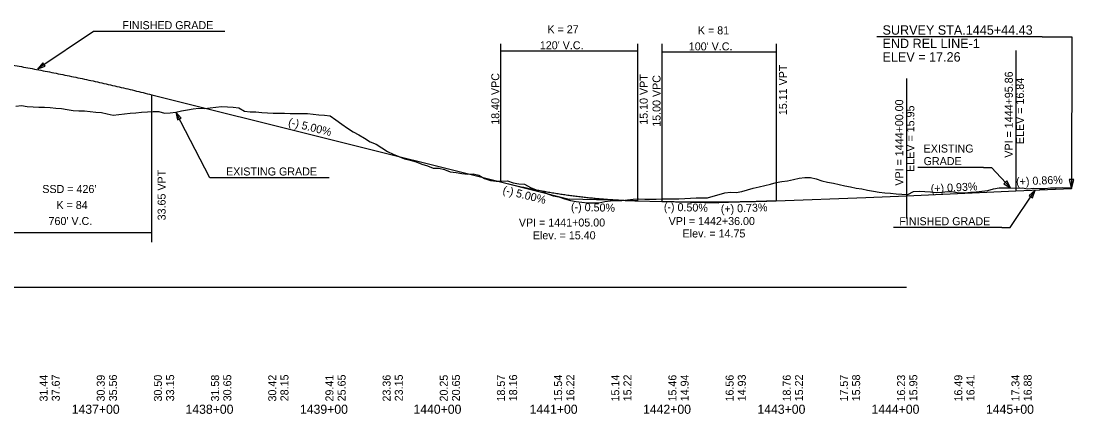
# Model space of a CAD drawing. Extents: x 2360994 to 2383826, y 330623 to 403123.
# Drawn here: x 2371951 to 2372872, y 366762 to 367106 of the extents above; entities that cross this region are included whole.
import ezdxf

# ---------------------------------------------------------------- set-up
doc = ezdxf.new("R2010")
doc.units = 0
for name, color, linetype in [('RD_DDB_GradeTX', 7, 'Continuous'), ('RD_DDB_Profile_EX', 7, 'Continuous'), ('RD_DDB_Profile_Lbl', 7, 'Continuous'), ('RD_DDB_Profile_PR', 7, 'Continuous'), ('RD_DDB_StaTX', 7, 'Continuous'), ('RD_DDB_StripGrade', 7, 'Continuous'), ('RD_DDB_VCLbl', 7, 'Continuous'), ('RD_GPK_Profile_Cell', 7, 'Continuous'), ('RD_TX_Profile', 7, 'Continuous')]:
    doc.layers.add(name, color=color, linetype=linetype)

msp = doc.modelspace()

# ---------------------------------------------------------------- linework, layer by layer
at = {"layer": 'RD_DDB_GradeTX'}
for p, q in [((2372370.57, 366964.89), (2372430.57, 366949.89)), ((2372490.57, 366948.39), (2372430.57, 366949.89)), ((2372611.57, 366948.45), (2372561.57, 366946.62)), ((2372511.57, 366947.87), (2372561.57, 366946.62))]:
    msp.add_line(p, q, dxfattribs=at)
at = {"layer": 'RD_DDB_Profile_EX'}
for points in [[(2371946.72, 367031.26), (2371951.72, 367031.76), (2371956.72, 367031), (2371961.72, 367030.54), (2371966.72, 367030.42), (2371971.72, 367030.28), (2371976.72, 367030.02)], [(2371976.72, 367030.02), (2371981.72, 367029.34), (2371986.72, 367029), (2371991.72, 367028.25), (2371996.72, 367027.32), (2372001.72, 367027.07), (2372006.72, 367027.05), (2372011.72, 367026.38), (2372016.72, 367025.94), (2372021.72, 367025.65), (2372026.72, 367024.56), (2372031.72, 367023.37), (2372036.72, 367023.94), (2372041.72, 367024.53), (2372046.72, 367025), (2372051.72, 367025.48), (2372056.72, 367025.93), (2372061.72, 367026.21), (2372066.72, 367026.36), (2372071.72, 367026.36), (2372076.72, 367025.08), (2372081.72, 367025.38), (2372086.72, 367025.95), (2372091.72, 367027.03), (2372096.72, 367028.1), (2372101.72, 367028.86), (2372106.72, 367029.43), (2372111.72, 367029.13), (2372116.72, 367029.58), (2372121.72, 367030.28), (2372126.72, 367030.92), (2372131.72, 367030.66), (2372136.72, 367030.23), (2372141.72, 367029.74), (2372146.72, 367026.93), (2372151.72, 367026.17), (2372156.72, 367026.13), (2372161.72, 367025.59), (2372166.72, 367025.25), (2372171.72, 367024.95), (2372176.72, 367024.96), (2372181.72, 367024.92), (2372186.72, 367024.74), (2372191.72, 367024.7), (2372196.72, 367024.79), (2372201.72, 367024.73), (2372206.72, 367024.29), (2372211.72, 367023.73), (2372216.72, 367023.2), (2372221.72, 367022.66), (2372226.72, 367019.11), (2372231.72, 367015.3), (2372236.72, 367011.82), (2372241.72, 367008.71), (2372246.72, 367006.17), (2372251.72, 367003.05), (2372256.72, 367000.08), (2372261.72, 366997.89), (2372266.72, 366994.76), (2372271.72, 366991.64), (2372276.72, 366989.1), (2372281.72, 366987.1), (2372286.72, 366985.04), (2372291.72, 366983.96), (2372296.72, 366982.33), (2372301.72, 366980.49), (2372306.72, 366979.06), (2372311.72, 366977.05), (2372316.72, 366976.79), (2372321.72, 366975.76), (2372326.72, 366973.68), (2372331.72, 366973.15), (2372336.72, 366972.32), (2372341.72, 366971.82), (2372346.72, 366972.04), (2372351.72, 366970.78), (2372356.72, 366967.78), (2372361.72, 366966.05), (2372366.72, 366965.63), (2372371.72, 366965.55), (2372376.72, 366965.8), (2372381.72, 366964.07), (2372386.72, 366963.23), (2372391.72, 366962.94), (2372396.72, 366959.98), (2372401.72, 366958), (2372406.72, 366957.09), (2372411.72, 366954.58), (2372416.72, 366952.69), (2372421.72, 366951.75), (2372426.72, 366950.23), (2372431.72, 366948.55), (2372436.72, 366947.84), (2372441.72, 366947.11), (2372446.72, 366946.49), (2372451.72, 366946.46), (2372456.72, 366946.7), (2372461.72, 366947.83), (2372466.72, 366948.2), (2372471.72, 366948.49), (2372476.72, 366948.64)], [(2372476.72, 366948.64), (2372481.72, 366949.22), (2372486.72, 366949.83), (2372491.72, 366950.09), (2372496.72, 366949.94), (2372501.72, 366949.75), (2372506.72, 366949.79), (2372511.72, 366949.99), (2372516.72, 366950.13), (2372521.72, 366950.12), (2372526.72, 366950.22), (2372531.72, 366950.4), (2372536.72, 366950.65), (2372541.72, 366950.97), (2372546.72, 366950.95), (2372551.72, 366951.1), (2372556.72, 366952.29), (2372561.72, 366954.01), (2372566.72, 366955.33), (2372571.72, 366955.83), (2372576.72, 366955.66), (2372581.72, 366956.53), (2372586.72, 366958), (2372591.72, 366959.39), (2372596.72, 366960.58), (2372601.72, 366961.85), (2372606.72, 366963.05), (2372611.72, 366964.28), (2372616.72, 366965.21), (2372621.72, 366965.8), (2372626.72, 366966.95), (2372631.72, 366968.1), (2372636.72, 366968.63), (2372641.72, 366968.62), (2372646.72, 366967.68), (2372651.72, 366965.72), (2372656.72, 366964.73), (2372661.72, 366963.8), (2372666.72, 366962.73), (2372671.72, 366961.44), (2372676.72, 366960.5), (2372681.72, 366959.53), (2372686.72, 366958.71), (2372691.72, 366957.59), (2372696.72, 366956.71), (2372701.72, 366955.9), (2372706.72, 366955.34), (2372711.72, 366954.96), (2372716.72, 366954.55), (2372721.72, 366954.25), (2372726.72, 366953.95), (2372731.72, 366956.59), (2372736.72, 366956.8), (2372741.72, 366956.65), (2372746.72, 366956.2), (2372751.72, 366955.77), (2372756.72, 366956.04), (2372761.72, 366956.47), (2372766.72, 366956.18), (2372771.72, 366955.45), (2372776.72, 366955.3), (2372781.72, 366955.83), (2372786.72, 366956.22), (2372791.72, 366956.9), (2372796.72, 366957.44), (2372801.72, 366958.75), (2372806.72, 366959.59), (2372811.72, 366959.77), (2372816.72, 366959.6), (2372821.72, 366959.42), (2372826.72, 366959.6), (2372831.72, 366958.76), (2372836.72, 366959.34), (2372841.72, 366959.1), (2372846.72, 366959.23), (2372851.72, 366959.71), (2372856.72, 366959.82), (2372861.72, 366959.87), (2372866.72, 366959.69), (2372870, 366959.75)]]:
    msp.add_lwpolyline(points, dxfattribs=at)
at = {"layer": 'RD_DDB_Profile_Lbl'}
for p, q in [((2372821.43, 367079.94), (2372821.43, 366981.08)), ((2372725.57, 367055.51), (2372725.57, 366956.58))]:
    msp.add_line(p, q, dxfattribs=at)
for points in [[(2372821.43, 366981.08), (2372821.43, 366957.08)], [(2372725.57, 366956.58), (2372725.57, 366932.88)]]:
    msp.add_lwpolyline(points, dxfattribs=at)
at = {"layer": 'RD_DDB_Profile_PR'}
for p, q in [((2372065.57, 367041.14), (2372370.57, 366964.89)), ((2372821.43, 366957.08), (2372870, 366959.18)), ((2372490.57, 366948.39), (2372511.57, 366947.87)), ((2372611.57, 366948.45), (2372690.09, 366951.33)), ((2372690.09, 366951.33), (2372725.57, 366952.63)), ((2372725.57, 366952.63), (2372821.43, 366957.08))]:
    msp.add_line(p, q, dxfattribs=at)
for points in [[(2371305.57, 367059.54), (2371320.77, 367062.54), (2371335.97, 367065.4), (2371351.17, 367068.12), (2371366.37, 367070.7), (2371381.57, 367073.15), (2371396.77, 367075.46), (2371411.97, 367077.63), (2371427.17, 367079.66), (2371442.37, 367081.56), (2371457.57, 367083.32), (2371472.77, 367084.94), (2371487.97, 367086.43), (2371503.17, 367087.78), (2371518.37, 367088.99), (2371533.57, 367090.06), (2371548.77, 367091), (2371563.97, 367091.79), (2371579.17, 367092.46), (2371594.37, 367092.98), (2371609.57, 367093.37), (2371624.77, 367093.62), (2371639.97, 367093.73), (2371655.17, 367093.71), (2371670.37, 367093.54), (2371685.57, 367093.24), (2371700.77, 367092.81), (2371715.97, 367092.23), (2371731.17, 367091.52), (2371746.37, 367090.67), (2371761.57, 367089.69), (2371776.77, 367088.57), (2371791.97, 367087.31), (2371807.17, 367085.91), (2371822.37, 367084.37), (2371837.57, 367082.7), (2371852.77, 367080.89), (2371867.97, 367078.94), (2371883.17, 367076.86), (2371898.37, 367074.64), (2371913.57, 367072.28), (2371928.77, 367069.78), (2371943.97, 367067.15), (2371959.17, 367064.38), (2371974.37, 367061.47), (2371989.57, 367058.43), (2372004.77, 367055.25), (2372019.97, 367051.93), (2372035.17, 367048.47), (2372050.37, 367044.88), (2372065.57, 367041.14)], [(2372370.57, 366964.89), (2372372.97, 366964.3), (2372375.37, 366963.72), (2372377.77, 366963.14), (2372380.17, 366962.58), (2372382.57, 366962.03), (2372384.97, 366961.49), (2372387.37, 366960.96), (2372389.77, 366960.44), (2372392.17, 366959.93), (2372394.57, 366959.43), (2372396.97, 366958.95), (2372399.37, 366958.47), (2372401.77, 366958.01), (2372404.17, 366957.55), (2372406.57, 366957.11), (2372408.97, 366956.68), (2372411.37, 366956.26), (2372413.77, 366955.84), (2372416.17, 366955.44), (2372418.57, 366955.05), (2372420.97, 366954.68), (2372423.37, 366954.31), (2372425.77, 366953.95), (2372428.17, 366953.61), (2372430.57, 366953.27), (2372432.97, 366952.95), (2372435.37, 366952.63), (2372437.77, 366952.33), (2372440.17, 366952.04), (2372442.57, 366951.75), (2372444.97, 366951.48), (2372447.37, 366951.22), (2372449.77, 366950.98), (2372452.17, 366950.74), (2372454.57, 366950.51), (2372456.97, 366950.29), (2372459.37, 366950.09), (2372461.77, 366949.89), (2372464.17, 366949.71), (2372466.57, 366949.53), (2372468.97, 366949.37), (2372471.37, 366949.22), (2372473.77, 366949.08), (2372476.17, 366948.95), (2372478.57, 366948.83), (2372480.97, 366948.72), (2372483.37, 366948.62), (2372485.77, 366948.54), (2372488.17, 366948.46), (2372490.57, 366948.39)], [(2372511.57, 366947.87), (2372513.57, 366947.82), (2372515.57, 366947.77), (2372517.57, 366947.73), (2372519.57, 366947.69), (2372521.57, 366947.65), (2372523.57, 366947.61), (2372525.57, 366947.58), (2372527.57, 366947.55), (2372529.57, 366947.52), (2372531.57, 366947.49), (2372533.57, 366947.47), (2372535.57, 366947.45), (2372537.57, 366947.43), (2372539.57, 366947.41), (2372541.57, 366947.4), (2372543.57, 366947.39), (2372545.57, 366947.38), (2372547.57, 366947.37), (2372549.57, 366947.36), (2372551.57, 366947.36), (2372553.57, 366947.36), (2372555.57, 366947.37), (2372557.57, 366947.37), (2372559.57, 366947.38), (2372561.57, 366947.39), (2372563.57, 366947.4), (2372565.57, 366947.42), (2372567.57, 366947.44), (2372569.57, 366947.46), (2372571.57, 366947.48), (2372573.57, 366947.5), (2372575.57, 366947.53), (2372577.57, 366947.56), (2372579.57, 366947.6), (2372581.57, 366947.63), (2372583.57, 366947.67), (2372585.57, 366947.71), (2372587.57, 366947.75), (2372589.57, 366947.8), (2372591.57, 366947.84), (2372593.57, 366947.89), (2372595.57, 366947.95), (2372597.57, 366948), (2372599.57, 366948.06), (2372601.57, 366948.12), (2372603.57, 366948.18), (2372605.57, 366948.24), (2372607.57, 366948.31), (2372609.57, 366948.38), (2372611.57, 366948.45)]]:
    msp.add_spline(points, degree=3, dxfattribs=at)
at = {"layer": 'RD_DDB_VCLbl'}
for p, q in [((2372370.57, 367085.65), (2372370.57, 366964.89)), ((2372370.57, 367079.68), (2372490.57, 367079.68)), ((2372490.57, 367085.65), (2372490.57, 366948.39)), ((2372511.57, 367085.65), (2372511.57, 366947.87)), ((2372511.57, 367078.73), (2372611.57, 367078.73)), ((2372611.57, 367085.65), (2372611.57, 366948.45)), ((2372065.57, 366912.13), (2372065.57, 367041.14)), ((2371305.57, 366920.55), (2372065.57, 366920.55))]:
    msp.add_line(p, q, dxfattribs=at)
at = {"layer": 'RD_GPK_Profile_Cell'}
msp.add_line((2368825.57, 366872.88), (2372725.57, 366872.88), dxfattribs=at)
at = {"layer": 'RD_TX_Profile'}
for p, q in [((2372129.4, 367096.54), (2372034.84, 367096.54)), ((2372844.29, 367091.92), (2372699.73, 367091.92)), ((2372792.94, 366977.61), (2372735.67, 366977.61)), ((2372220.67, 366968.51), (2372125.55, 366968.51)), ((2372808.96, 366925), (2372714.39, 366925))]:
    msp.add_line(p, q, dxfattribs=at)
for points in [[(2372034.84, 367096.54), (2372014.51, 367096.54), (2371965.81, 367063.8)], [(2372844.29, 367091.92), (2372870.28, 367091.92), (2372870, 366959.18)], [(2372125.55, 366968.51), (2372116.41, 366968.51), (2372086.72, 367025.95)], [(2372792.94, 366977.61), (2372800.03, 366977.61), (2372816.72, 366959.6)], [(2372808.96, 366925), (2372816.51, 366925), (2372838.11, 366957.54)]]:
    msp.add_lwpolyline(points, dxfattribs=at)
for points in [[(2371970.41, 367069.08), (2371965.81, 367063.8), (2371972.43, 367066.07)], [(2372091.43, 367020.78), (2372086.72, 367025.95), (2372088.21, 367019.11)], [(2372867.88, 366967.14), (2372870, 366959.18), (2372872.14, 366967.13)], [(2372810.79, 366963.33), (2372816.72, 366959.6), (2372813.45, 366965.79)], [(2372835.88, 366950.9), (2372838.11, 366957.54), (2372832.86, 366952.91)]]:
    msp.add_lwpolyline(points, close=True, dxfattribs=at)

# ---------------------------------------------------------------- texts
at = {"layer": 'RD_DDB_GradeTX'}
for s, rotation, p in [('(-) 5.00%', 345.96376, (2372184.49, 367014.28)), ('(+) 0.86%', 2.47573, (2372821.68, 366961.71)), ('(-) 5.00%', 345.96376, (2372372.03, 366954.87)), ('(+) 0.93%', 2.65787, (2372747.05, 366955.63)), ('(-) 0.50%', 358.5679, (2372432.18, 366939.64)), ('(-) 0.50%', 358.5679, (2372513.39, 366939.64)), ('(+) 0.73%', 2.0994, (2372563.38, 366937.75))]:
    msp.add_text(s, height=7, rotation=rotation, dxfattribs=at).set_placement(p)
at = {"layer": 'RD_DDB_Profile_Lbl'}
for s, p in [('VPI = 1444+95.86', (2372818.67, 366986.08)), ('ELEV = 16.84', (2372828.43, 366997.97)), ('VPI = 1444+00.00', (2372722.81, 366961.58)), ('ELEV = 15.95', (2372732.57, 366973.69))]:
    msp.add_text(s, height=7, rotation=90, dxfattribs=at).set_placement(p)
for s, p in [('VPI = 1441+05.00', (2372386.65, 366925.86)), ('VPI = 1442+36.00', (2372517.65, 366927.16)), ('Elev. = 15.40', (2372398.89, 366914.68)), ('Elev. = 14.75', (2372529.88, 366916.29))]:
    msp.add_text(s, height=7, dxfattribs=at).set_placement(p)
at = {"layer": 'RD_DDB_StaTX'}
for s, p in [('1437+00', (2371995.57, 366762)), ('1438+00', (2372095.11, 366762)), ('1439+00', (2372195.21, 366762)), ('1440+00', (2372294.46, 366762)), ('1441+00', (2372396.08, 366762)), ('1442+00', (2372495.28, 366762)), ('1443+00', (2372595.31, 366762)), ('1444+00', (2372695.06, 366762)), ('1445+00', (2372795.2, 366762))]:
    msp.add_text(s, height=8, dxfattribs=at).set_placement(p)
at = {"layer": 'RD_DDB_StripGrade'}
for s, p in [('18.40 VPC', (2372369.57, 367014.89)), ('15.10 VPT', (2372499.34, 367014.89)), ('15.11 VPT', (2372621.15, 367023.31)), ('15.00 VPC', (2372510.57, 367013.12)), ('33.65 VPT', (2372077.7, 366931.25)), ('31.44', (2371974.48, 366772.77)), ('37.67', (2371985.15, 366772.95)), ('30.39', (2372024.48, 366772.77)), ('35.56', (2372035.15, 366772.95)), ('30.50', (2372074.48, 366772.77)), ('33.15', (2372085.15, 366772.95)), ('31.58', (2372124.48, 366772.77)), ('30.65', (2372135.15, 366772.95)), ('30.42', (2372174.48, 366772.77)), ('28.15', (2372185.15, 366772.95)), ('29.41', (2372224.48, 366772.77)), ('25.65', (2372235.15, 366772.95)), ('23.36', (2372274.48, 366772.77)), ('23.15', (2372285.15, 366772.95)), ('20.25', (2372324.48, 366772.77)), ('20.65', (2372335.15, 366772.95)), ('18.57', (2372374.48, 366772.77)), ('18.16', (2372385.15, 366772.95)), ('15.54', (2372424.48, 366772.77)), ('16.22', (2372435.15, 366772.95)), ('15.14', (2372474.48, 366772.77)), ('15.22', (2372485.15, 366772.95)), ('15.46', (2372524.48, 366772.77)), ('14.94', (2372535.15, 366772.95)), ('16.56', (2372574.48, 366772.77)), ('14.93', (2372585.15, 366772.95)), ('18.76', (2372624.48, 366772.77)), ('15.22', (2372635.15, 366772.95)), ('17.57', (2372674.48, 366772.77)), ('15.58', (2372685.15, 366772.95)), ('16.23', (2372724.48, 366772.77)), ('15.95', (2372735.15, 366772.95)), ('16.49', (2372774.48, 366772.77)), ('16.41', (2372785.15, 366772.95)), ('17.34', (2372824.48, 366772.77)), ('16.88', (2372835.15, 366772.95))]:
    msp.add_text(s, height=7, rotation=90, dxfattribs=at).set_placement(p)
at = {"layer": 'RD_DDB_VCLbl'}
for s, p in [('K = 27', (2372411.65, 367094.93)), ('K = 81', (2372543.24, 367093.98)), ("120' V.C.", (2372405.01, 367080.93)), ("100' V.C.", (2372535.29, 367079.98)), ("SSD = 426'", (2371969.86, 366955.2)), ('K = 84', (2371982.24, 366941.2)), ("760' V.C.", (2371975.31, 366927.2))]:
    msp.add_text(s, height=7, dxfattribs=at).set_placement(p)
at = {"layer": 'RD_TX_Profile'}
for s, height, p in [('FINISHED GRADE', 7, (2372039.84, 367098.54)), ('SURVEY STA.1445+44.43', 8.2353, (2372704.73, 367093.68)), ('END REL LINE-1', 8.2353, (2372704.73, 367081.92)), ('ELEV = 17.26', 8.2353, (2372704.73, 367070.16)), ('EXISTING', 7, (2372740.67, 366990.61)), ('GRADE', 7, (2372740.67, 366979.61)), ('EXISTING GRADE', 7, (2372130.55, 366970.51)), ('FINISHED GRADE', 7, (2372719.39, 366927))]:
    msp.add_text(s, height=height, dxfattribs=at).set_placement(p)

doc.saveas('drawing.dxf')
